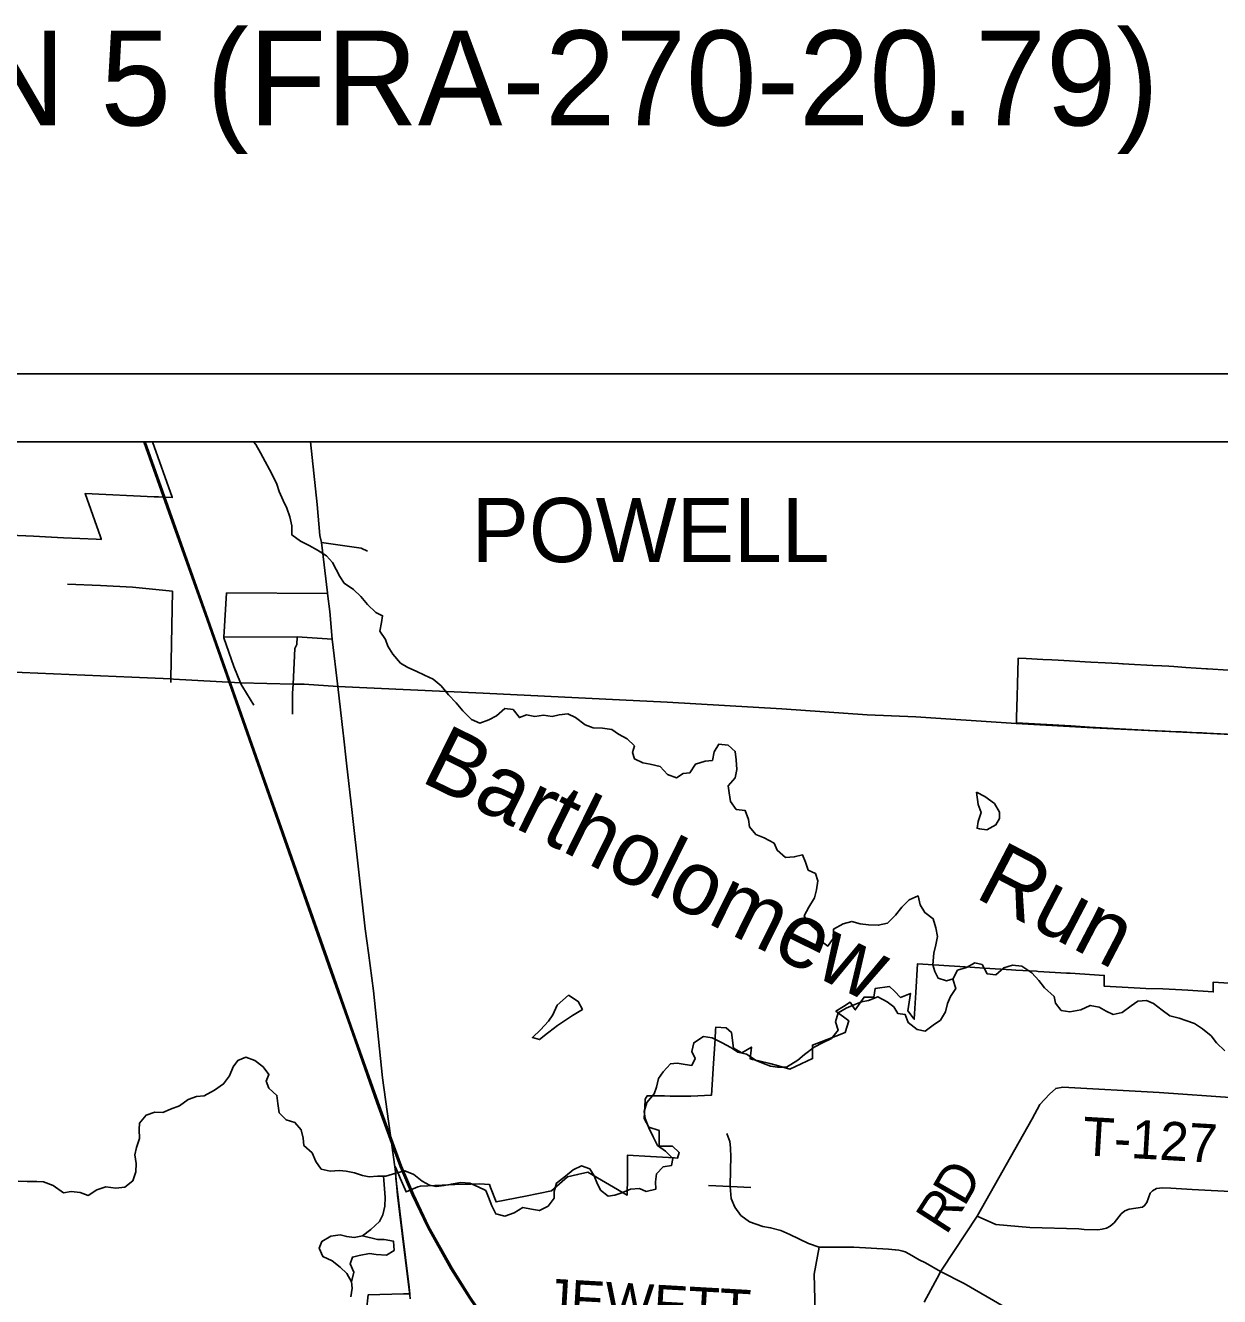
# Model space of a CAD drawing. Extents: x 0 to 34, y 0 to 22.
# Drawn here: x 15.645 to 17.407, y 8.924 to 10.798 of the extents above; entities that cross this region are included whole.
import ezdxf

# ---------------------------------------------------------------- set-up
doc = ezdxf.new("R2010")
doc.units = 0
for name, color, linetype in [('Default', 7, 'Continuous'), ('GM_X_City_Street', 7, 'Continuous'), ('GM_X_Corporation', 7, 'Continuous'), ('GM_X_Corporation_Text', 7, 'Continuous'), ('GM_X_County_Road', 7, 'Continuous'), ('GM_X_Minor_Lake', 7, 'Continuous'), ('GM_X_Minor_River', 7, 'Continuous'), ('GM_X_Minor_River_Text', 7, 'Continuous'), ('GM_X_Rail_Line', 7, 'Continuous'), ('GM_X_State_Route', 7, 'Continuous'), ('GM_X_Township_Road', 7, 'Continuous'), ('GM_X_Township_Road_Text', 7, 'Continuous'), ('SH_Data', 7, 'Continuous')]:
    doc.layers.add(name, color=color, linetype=linetype)

msp = doc.modelspace()

# ---------------------------------------------------------------- linework, layer by layer
at = {"layer": 'GM_X_City_Street'}
msp.add_line((15.942, 9.9613), (16.0909, 9.9604), dxfattribs=at)
for points in [[(16.0821, 10.0353), (16.1403, 10.0271), (16.1498, 10.0225)], [(15.7076, 9.9739), (15.7561, 9.9721), (15.8034, 9.9696), (15.8625, 9.9639)], [(15.8596, 9.8293), (15.8597, 9.8344), (15.8625, 9.9639)], [(15.9823, 9.7959), (15.9658, 9.8224), (15.9641, 9.825), (15.9626, 9.8287), (15.9527, 9.8525), (15.9381, 9.8949), (15.9382, 9.8961), (15.942, 9.9613)], [(15.9382, 9.8961), (16.046, 9.8964), (16.098, 9.8932)], [(16.0393, 9.8132), (16.04, 9.8268), (16.0427, 9.8792), (16.0457, 9.8849), (16.046, 9.8964)], [(16.0393, 9.7822), (16.0393, 9.8121), (16.0393, 9.8132)]]:
    msp.add_lwpolyline(points, dxfattribs=at)
at = {"layer": 'GM_X_Corporation'}
for points in [[(15.3473, 8.5302), (16.0546, 8.4904), (16.2652, 8.4813), (16.5003, 8.4668), (16.6112, 8.4601), (16.8906, 8.4459), (17.9061, 8.3935), (17.9129, 8.3931), (18.0835, 8.3895), (18.0903, 8.3893), (19.1791, 8.3374), (19.2255, 8.335), (19.3372, 8.3286), (19.3853, 8.3266), (19.4457, 8.3236), (19.4724, 8.3227), (19.4766, 8.3225), (19.5203, 8.3202), (19.5346, 8.3197), (19.5646, 8.318), (19.5646, 10.1841), (12.7646, 10.1841)], [(15.3473, 8.5302), (16.0546, 8.4904), (16.2652, 8.4813), (16.5003, 8.4668), (16.6112, 8.4601), (16.8906, 8.4459), (17.9061, 8.3935), (17.9129, 8.3931), (17.9187, 8.5404), (17.9296, 8.8181), (17.9647, 9.7099), (17.9872, 10.1841), (13.2832, 10.1841)], [(17.8098, 10.1841), (15.833, 10.1841), (15.8618, 10.1025), (15.8621, 10.1018), (15.8418, 10.1027), (15.835, 10.1031), (15.7337, 10.1076), (15.7334, 10.1076), (15.7559, 10.0439), (15.7571, 10.0407), (15.7573, 10.04), (15.7498, 10.0403), (15.7014, 10.0426), (15.6838, 10.0434), (15.6572, 10.0447), (15.5762, 10.0485)], [(17.4378, 9.752), (17.3878, 9.7544), (17.381, 9.7547), (17.366, 9.7554), (17.3506, 9.7562), (17.3345, 9.7569), (17.3261, 9.7572), (17.3039, 9.7584), (17.2149, 9.7632), (17.1871, 9.7652), (17.1068, 9.7694), (17.1068, 9.77), (17.107, 9.7754), (17.1071, 9.7775), (17.108, 9.8085), (17.1086, 9.8269), (17.1091, 9.8452), (17.1097, 9.8636), (17.1097, 9.865), (17.1211, 9.8644), (17.1457, 9.8631), (17.1591, 9.8624), (17.1683, 9.8619), (17.1854, 9.8609), (17.2005, 9.8601), (17.2082, 9.8597), (17.2166, 9.8592), (17.2377, 9.8581), (17.2573, 9.857), (17.2633, 9.8567), (17.2642, 9.8567), (17.2813, 9.8557), (17.2993, 9.8548), (17.3082, 9.8543), (17.3215, 9.8536), (17.3319, 9.853), (17.339, 9.8526), (17.3569, 9.8512), (17.3873, 9.8494), (17.3888, 9.8493), (17.4199, 9.8475)], [(16.1484, 8.9035), (16.151, 8.9262), (16.2028, 8.9276), (16.2075, 8.9277), (16.2123, 8.9278), (16.2111, 8.9373), (16.2058, 8.9811), (16.2015, 9.0173), (16.1917, 9.0983), (16.1908, 9.1156), (16.1908, 9.1156), (16.196, 9.103), (16.1979, 9.0984), (16.2052, 9.0813), (16.2068, 9.0778), (16.2242, 9.0852), (16.2278, 9.0866), (16.26, 9.0879), (16.2789, 9.0889), (16.3022, 9.0895), (16.3149, 9.0897), (16.3296, 9.0889), (16.3314, 9.0842), (16.3396, 9.0631), (16.3828, 9.0718), (16.4211, 9.0796), (16.4447, 9.0999), (16.4597, 9.1034), (16.4748, 9.107), (16.5329, 9.0732), (16.533, 9.0848), (16.5331, 9.0873), (16.5335, 9.1321), (16.5671, 9.1302), (16.6028, 9.1281), (16.6071, 9.1279), (16.6097, 9.1362), (16.5997, 9.1452), (16.5798, 9.1456), (16.58, 9.1686), (16.565, 9.1734), (16.5581, 9.1861), (16.5588, 9.2026), (16.5594, 9.2145), (16.5622, 9.2195), (16.5879, 9.2196), (16.5962, 9.2192), (16.6266, 9.2192), (16.6571, 9.2204), (16.6597, 9.2594), (16.6597, 9.2599), (16.6624, 9.3035), (16.6633, 9.3168), (16.6635, 9.3207), (16.6786, 9.3197), (16.6865, 9.313), (16.6899, 9.2897), (16.7021, 9.2832), (16.7161, 9.2914), (16.7141, 9.2742), (16.7178, 9.2733), (16.7269, 9.2711), (16.7433, 9.2672), (16.7527, 9.2646), (16.7728, 9.2591), (16.8062, 9.2744), (16.806, 9.2943), (16.8408, 9.3077), (16.8544, 9.313), (16.8597, 9.3303), (16.8407, 9.3443), (16.8519, 9.3514), (16.8615, 9.3575), (16.8692, 9.3463), (16.8822, 9.3652), (16.8968, 9.3649), (16.8986, 9.3781), (16.9197, 9.3808), (16.9269, 9.3737), (16.9361, 9.3646), (16.9506, 9.3705), (16.9467, 9.3447), (16.9562, 9.3325), (16.9585, 9.3719), (16.961, 9.4142), (17.0311, 9.4098), (17.0599, 9.408), (17.0995, 9.4055), (17.1061, 9.4051), (17.1364, 9.4032), (17.1391, 9.4031), (17.1808, 9.4007), (17.1864, 9.4003), (17.2364, 9.3971), (17.2364, 9.3812), (17.2893, 9.3783), (17.298, 9.3778), (17.3229, 9.3775), (17.3511, 9.3757), (17.3599, 9.3752), (17.3971, 9.3729), (17.3972, 9.3835), (17.3972, 9.3873), (17.4207, 9.3859)]]:
    msp.add_lwpolyline(points, dxfattribs=at)
at = {"layer": 'GM_X_County_Road'}
msp.add_line((16.1138, 9.7546), (16.1062, 9.8233), dxfattribs=at)
for points in [[(16.0908, 9.9614), (16.0821, 10.0353), (16.0795, 10.046), (16.0758, 10.0915), (16.0659, 10.1841)], [(16.1062, 9.8233), (16.098, 9.8932), (16.0945, 9.9337), (16.0909, 9.9604), (16.0908, 9.9614)], [(16.1513, 9.4305), (16.1464, 9.466), (16.1274, 9.6375), (16.1188, 9.7102), (16.1143, 9.7506), (16.1138, 9.7546)], [(16.1911, 9.107), (16.1903, 9.115), (16.1721, 9.2462), (16.1589, 9.3743), (16.1513, 9.4305)], [(16.1996, 9.0283), (16.1942, 9.0731), (16.1911, 9.107)], [(16.2128, 8.9204), (16.2121, 8.9262), (16.2053, 8.9805), (16.201, 9.0167), (16.1996, 9.0283)]]:
    msp.add_lwpolyline(points, dxfattribs=at)
at = {"layer": 'GM_X_Minor_Lake'}
for points in [[(17.048, 9.6672), (17.0507, 9.649), (17.0548, 9.6372), (17.0507, 9.6243), (17.0488, 9.6141), (17.0525, 9.6135)], [(17.0525, 9.6135), (17.0632, 9.6118), (17.0768, 9.619), (17.0821, 9.6285), (17.0821, 9.638), (17.0745, 9.6505), (17.0605, 9.6608), (17.048, 9.6672)], [(16.4464, 9.3678), (16.4298, 9.3534), (16.423, 9.339), (16.4169, 9.3295), (16.4052, 9.317), (16.3931, 9.3056), (16.4037, 9.3026), (16.4154, 9.312)], [(16.4154, 9.312), (16.4173, 9.3136), (16.4302, 9.3231), (16.4521, 9.3382), (16.4669, 9.347), (16.4608, 9.3587), (16.4464, 9.3678)], [(16.1423, 9.0129), (16.1302, 9.0106), (16.1192, 9.0121), (16.1094, 9.0144), (16.0958, 9.0125), (16.0825, 9.0049), (16.0787, 8.9951), (16.084, 8.9826), (16.0977, 8.9761), (16.1094, 8.967), (16.1196, 8.9575), (16.1265, 8.9453)], [(16.1265, 8.9453), (16.1295, 8.9598), (16.1242, 8.9719), (16.1276, 8.9818), (16.1374, 8.984), (16.1529, 8.9871), (16.1628, 8.9855), (16.1779, 8.9844), (16.1893, 8.9916), (16.1881, 9.0053), (16.1745, 9.0075), (16.1646, 9.0079), (16.1423, 9.0129)]]:
    msp.add_lwpolyline(points, dxfattribs=at)
at = {"layer": 'GM_X_Minor_River'}
for points in [[(16.1801, 9.8828), (16.1763, 9.8923), (16.168, 9.9049), (16.1706, 9.9174), (16.1721, 9.9276), (16.1623, 9.9325), (16.1498, 9.9439), (16.14, 9.9561), (16.129, 9.966), (16.1157, 9.9758), (16.1093, 9.9853), (16.1036, 9.9956), (16.0983, 10.0058), (16.0892, 10.0161), (16.076, 10.0244), (16.0638, 10.0312), (16.051, 10.0373), (16.0385, 10.0468), (16.0381, 10.0601), (16.0354, 10.0734), (16.0309, 10.0863), (16.0256, 10.0973), (16.0195, 10.1106), (16.0161, 10.1216), (16.0119, 10.131), (16.0055, 10.1432), (15.9991, 10.1549), (15.9922, 10.1679), (15.9851, 10.18), (15.9816, 10.1841)], [(17.0134, 9.392), (17.0039, 9.3891), (16.9917, 9.3929), (16.9868, 9.4028), (16.9838, 9.4126), (16.9853, 9.4301), (16.9883, 9.4422), (16.9906, 9.4544), (16.9883, 9.4673), (16.9841, 9.4806), (16.9716, 9.4897), (16.9648, 9.5011), (16.9618, 9.5143), (16.9489, 9.5087), (16.9379, 9.4977), (16.9285, 9.4859), (16.9168, 9.4742), (16.9031, 9.4711), (16.8888, 9.4715), (16.8767, 9.4734), (16.8642, 9.4768), (16.8513, 9.4731), (16.8373, 9.4655), (16.8365, 9.4514), (16.8286, 9.4404), (16.8169, 9.4492), (16.8135, 9.4625), (16.801, 9.4735), (16.7941, 9.4849), (16.8006, 9.4977), (16.8093, 9.5114), (16.8119, 9.5232), (16.8142, 9.5364), (16.8104, 9.5474), (16.7998, 9.5524), (16.796, 9.5642), (16.7915, 9.5748), (16.7793, 9.5718), (16.7665, 9.571), (16.754, 9.5816), (16.7494, 9.5923), (16.7351, 9.6002), (16.7226, 9.6048), (16.7135, 9.6162), (16.712, 9.6272), (16.707, 9.6401), (16.6938, 9.642), (16.6851, 9.6538), (16.6835, 9.6663), (16.682, 9.6765), (16.6919, 9.6887), (16.6945, 9.7008), (16.6937, 9.7148), (16.6922, 9.7274), (16.682, 9.7365), (16.668, 9.738), (16.6612, 9.727), (16.6585, 9.7141), (16.648, 9.713), (16.6336, 9.7088), (16.6253, 9.6959), (16.6154, 9.6948), (16.6056, 9.6887), (16.5923, 9.6933), (16.5814, 9.705), (16.5666, 9.7088), (16.556, 9.7108), (16.5435, 9.7165), (16.5408, 9.7259), (16.5435, 9.7358), (16.5329, 9.7461), (16.52, 9.7529), (16.5102, 9.7597), (16.4965, 9.7616), (16.4829, 9.7624), (16.4708, 9.7666), (16.4568, 9.7776), (16.4451, 9.7829), (16.4326, 9.7814), (16.422, 9.7791), (16.4095, 9.7807), (16.3966, 9.7791), (16.3845, 9.7814), (16.3739, 9.7773), (16.3645, 9.7894), (16.3523, 9.7905), (16.3399, 9.7799), (16.3289, 9.7739), (16.3156, 9.7693), (16.3032, 9.7743), (16.2907, 9.7875), (16.2804, 9.7989), (16.2695, 9.8107), (16.2585, 9.824), (16.2467, 9.8339), (16.2339, 9.8399), (16.2214, 9.846), (16.2096, 9.8513), (16.1983, 9.8578), (16.1873, 9.8711), (16.1801, 9.8828)], [(17.4145, 9.2861), (17.402, 9.2978), (17.3941, 9.3081), (17.3816, 9.3183), (17.3695, 9.3263), (17.357, 9.3305), (17.3468, 9.3343), (17.3331, 9.3377), (17.3218, 9.3461), (17.3089, 9.3559), (17.2987, 9.3601), (17.2858, 9.3594), (17.276, 9.3525), (17.2627, 9.3423), (17.2495, 9.3396), (17.2393, 9.3446), (17.229, 9.3503), (17.2158, 9.3529), (17.2018, 9.3465), (17.1855, 9.3435), (17.173, 9.3454), (17.1647, 9.3564), (17.1628, 9.3659), (17.1484, 9.3788), (17.1401, 9.3898), (17.1295, 9.4008), (17.1151, 9.411), (17.1011, 9.4122), (17.0886, 9.4084), (17.0765, 9.3982), (17.0636, 9.3997), (17.0564, 9.4134), (17.0455, 9.4156), (17.0334, 9.4088), (17.0201, 9.4047), (17.0133, 9.3918), (17.0175, 9.3781), (17.0095, 9.3663), (17.0054, 9.3557), (17.0024, 9.3436), (16.9948, 9.3311), (16.9842, 9.3239), (16.9721, 9.3151), (16.9607, 9.3174), (16.9475, 9.3277), (16.9429, 9.3394), (16.932, 9.341), (16.9259, 9.3508), (16.9161, 9.358), (16.9024, 9.3656), (16.8888, 9.36), (16.8786, 9.3581), (16.8688, 9.3543), (16.8559, 9.349), (16.8438, 9.3418), (16.84, 9.3285), (16.8438, 9.3164), (16.834, 9.3042), (16.8211, 9.2978), (16.8086, 9.2913), (16.7946, 9.2803), (16.7844, 9.2724), (16.7678, 9.2618), (16.7545, 9.2618), (16.7443, 9.2633)], [(16.7443, 9.2633), (16.7341, 9.2675), (16.7231, 9.2717), (16.7087, 9.2808), (16.6962, 9.2842), (16.6856, 9.291), (16.6728, 9.2979), (16.658, 9.3051), (16.6455, 9.307), (16.6311, 9.2979), (16.6281, 9.285), (16.633, 9.2748), (16.6281, 9.2645), (16.6183, 9.266), (16.6065, 9.2679), (16.5967, 9.2668), (16.5857, 9.2551), (16.5789, 9.2452), (16.5763, 9.2323), (16.5725, 9.2224), (16.5619, 9.2099), (16.5578, 9.1966), (16.5593, 9.1864), (16.565, 9.1724), (16.5714, 9.1591), (16.5778, 9.1465), (16.5892, 9.1382), (16.6002, 9.1272), (16.5983, 9.1169), (16.5858, 9.115), (16.576, 9.1044), (16.5748, 9.093), (16.5752, 9.082), (16.5608, 9.0786), (16.551, 9.0828), (16.5378, 9.0821), (16.5249, 9.0764), (16.5147, 9.073), (16.5048, 9.0715), (16.4935, 9.0806), (16.4882, 9.092), (16.4844, 9.1018), (16.4776, 9.1121), (16.4655, 9.1163), (16.4534, 9.1106), (16.442, 9.1011), (16.4284, 9.0909), (16.4254, 9.0787), (16.425, 9.0689), (16.4163, 9.0567), (16.4034, 9.0503), (16.3917, 9.0526), (16.3792, 9.0548), (16.3663, 9.0473), (16.3523, 9.0423), (16.3391, 9.0454), (16.3334, 9.0572), (16.3285, 9.0701), (16.3243, 9.0799), (16.313, 9.0856), (16.3008, 9.0906), (16.2872, 9.0917), (16.2736, 9.0894), (16.263, 9.0876), (16.2509, 9.0857), (16.2411, 9.0879), (16.2305, 9.0936), (16.218, 9.1035), (16.2047, 9.1088), (16.1918, 9.1054), (16.1771, 9.1009), (16.1646, 9.1009), (16.1525, 9.1001), (16.1423, 9.102), (16.1305, 9.1062), (16.1184, 9.1085), (16.1086, 9.1096), (16.095, 9.1085), (16.0817, 9.1116), (16.0738, 9.1226), (16.0685, 9.1355), (16.056, 9.1461), (16.0548, 9.1571), (16.0522, 9.1693), (16.0427, 9.1803), (16.0298, 9.1844), (16.0196, 9.1947), (16.0177, 9.2083), (16.0162, 9.2201), (16.0044, 9.2311), (16.0003, 9.2414), (16.0044, 9.2512), (15.9961, 9.2622), (15.9836, 9.2717), (15.9704, 9.2767), (15.9586, 9.2717), (15.9518, 9.2623), (15.9465, 9.249), (15.9375, 9.2372), (15.9242, 9.2277), (15.9091, 9.2194)], [(15.9091, 9.2194), (15.8977, 9.2187), (15.8852, 9.2141), (15.8728, 9.205), (15.8595, 9.1997), (15.8482, 9.1948), (15.8364, 9.1955), (15.8232, 9.191), (15.8137, 9.1792), (15.813, 9.1698), (15.8137, 9.1569), (15.8092, 9.1436), (15.8066, 9.1326), (15.8085, 9.1197), (15.8081, 9.1075), (15.8039, 9.0943), (15.7918, 9.0848), (15.7786, 9.0833), (15.7642, 9.0852), (15.7506, 9.081), (15.7381, 9.0727), (15.726, 9.0768), (15.7127, 9.0784), (15.7014, 9.0765), (15.6862, 9.0875), (15.6722, 9.0928), (15.662, 9.0932), (15.648, 9.0932), (15.6348, 9.0939)], [(16.1737, 9.1009), (16.1741, 9.0952), (16.1748, 9.0823), (16.176, 9.0698), (16.1756, 9.0569), (16.1726, 9.044), (16.1677, 9.0345), (16.1548, 9.0224), (16.1423, 9.0129), (16.1302, 9.0106), (16.1192, 9.0121), (16.1094, 9.0144), (16.0958, 9.0125), (16.0825, 9.0049), (16.0787, 8.9951), (16.084, 8.9826), (16.0977, 8.9761), (16.1094, 8.967), (16.1196, 8.9575), (16.1265, 8.9453), (16.1272, 8.9359), (16.1253, 8.923)]]:
    msp.add_lwpolyline(points, dxfattribs=at)
at = {"layer": 'GM_X_Rail_Line'}
for points in [[(16.6916, 8.4543), (16.6646, 8.4903), (16.6063, 8.5579), (16.4536, 8.7316), (16.4089, 8.7825), (16.3706, 8.8265), (16.3479, 8.855), (16.3321, 8.8758), (16.316, 8.8981), (16.3002, 8.9211), (16.273, 8.9643), (16.2388, 9.0256), (16.2159, 9.0737), (16.1982, 9.1153), (16.1872, 9.1446), (16.1638, 9.2095), (16.1241, 9.3217), (16.0955, 9.4034), (15.9132, 9.9213), (15.854, 10.0881), (15.8202, 10.1841)], [(16.6931, 8.4555), (16.6661, 8.4914), (16.6077, 8.5592), (16.4551, 8.7329), (16.4103, 8.7837), (16.3721, 8.8277), (16.3494, 8.8562), (16.3337, 8.8769), (16.3175, 8.8992), (16.3018, 8.9221), (16.2747, 8.9653), (16.2404, 9.0265), (16.2176, 9.0745), (16.2, 9.116), (16.189, 9.1452), (16.1656, 9.2101), (16.1259, 9.3223), (16.0973, 9.404), (15.915, 9.9219), (15.8558, 10.0887), (15.8222, 10.1841)]]:
    msp.add_lwpolyline(points, dxfattribs=at)
at = {"layer": 'GM_X_State_Route'}
for points in [[(15.4875, 9.852), (15.5941, 9.8457), (15.8025, 9.8371), (15.8597, 9.8344), (15.8637, 9.8342), (15.9626, 9.8287), (16.04, 9.8268), (16.0564, 9.8264), (16.1062, 9.8233)], [(16.1062, 9.8233), (16.3203, 9.8132), (16.5918, 9.7999), (16.7609, 9.7904), (16.8869, 9.7812), (16.9585, 9.7783), (17.0993, 9.7693)], [(17.0993, 9.7693), (17.1064, 9.7688), (17.22, 9.7624), (17.4436, 9.7512)]]:
    msp.add_lwpolyline(points, dxfattribs=at)
at = {"layer": 'GM_X_Township_Road'}
for points in [[(16.9709, 8.9154), (16.9934, 8.9571), (16.995, 8.9605), (16.9973, 8.964), (17.0491, 9.0423), (17.1301, 9.1859), (17.1414, 9.2067), (17.1556, 9.2222), (17.165, 9.2306), (17.1754, 9.2324), (17.3175, 9.2244), (17.5407, 9.2088), (17.5686, 9.2108), (17.6382, 9.2067), (17.6571, 9.2056), (17.6812, 9.2025), (17.7099, 9.1965), (17.762, 9.184), (17.7893, 9.1797)], [(16.995, 8.9605), (16.9726, 8.9731), (16.9635, 8.9778), (16.9494, 8.9862), (16.9428, 8.9894), (16.9392, 8.9905), (16.9335, 8.9918), (16.9281, 8.9927), (16.9181, 8.9933), (16.867, 8.9963), (16.8161, 8.9966), (16.8003, 9.0018), (16.7729, 9.015), (16.7595, 9.0211), (16.7444, 9.025), (16.7328, 9.0269), (16.7135, 9.0336), (16.7005, 9.0433), (16.6916, 9.0552), (16.6861, 9.0684), (16.6848, 9.086), (16.6852, 9.1109), (16.6858, 9.1291), (16.6852, 9.1429), (16.6842, 9.1522), (16.6798, 9.1639)], [(16.6526, 9.0876), (16.6848, 9.086), (16.7151, 9.0846)], [(17.0491, 9.0423), (17.0764, 9.0297), (17.1268, 9.0252), (17.1989, 9.0237), (17.2066, 9.0226), (17.2269, 9.0222), (17.2333, 9.0228), (17.2396, 9.0246), (17.2454, 9.0275), (17.2513, 9.0324), (17.2616, 9.0455), (17.2668, 9.0502), (17.2734, 9.0525), (17.2927, 9.0554), (17.296, 9.0577), (17.2992, 9.0622), (17.3044, 9.076), (17.3074, 9.0794), (17.3133, 9.0828), (17.3226, 9.0839), (17.3348, 9.0834), (17.3663, 9.0816), (17.432, 9.0779)], [(16.8112, 8.8488), (16.8102, 8.9013), (16.8084, 8.9565), (16.8161, 8.9966)], [(17.0317, 8.8186), (17.0625, 8.8193), (17.07, 8.8202), (17.0836, 8.8241), (17.0939, 8.8308), (17.1003, 8.8374), (17.1042, 8.8436), (17.1083, 8.8528), (17.1105, 8.8605), (17.1108, 8.8712), (17.1065, 8.8877), (17.1017, 8.8965), (17.0954, 8.9035), (17.0886, 8.9091), (17.0299, 8.9428), (16.995, 8.9605)]]:
    msp.add_lwpolyline(points, dxfattribs=at)
at = {"layer": 'SH_Data'}
for p, q in [((12.6646, 10.2841), (19.6646, 10.2841)), ((12.7646, 10.1841), (19.5646, 10.1841))]:
    msp.add_line(p, q, dxfattribs=at)

# ---------------------------------------------------------------- texts
at = {"layer": 'Default'}
msp.add_text('LOCATION 5 (FRA-270-20.79)', height=0.14, dxfattribs=at).set_placement((14.7471, 10.6505))
at = {"layer": 'GM_X_Corporation_Text'}
msp.add_text('POWELL', height=0.0947, rotation=0, dxfattribs=at).set_placement((16.3034, 10.0066))
at = {"layer": 'GM_X_Minor_River_Text'}
for s, rotation, p in [('Bartholomew', 333.6958, (16.2261, 9.6842)), ('Run', 332.4029, (17.0434, 9.5132))]:
    msp.add_text(s, height=0.0947, rotation=rotation, dxfattribs=at).set_placement(p)
at = {"layer": 'GM_X_Township_Road_Text'}
for s, height, rotation, p in [('T-127', 0.05682, 356.6673, (17.2032, 9.1321)), ('D', 0.0568, 60.0129, (17.0301, 9.0548)), ('R', 0.0568, 57.2344, (17.0033, 9.013)), ('JEWETT', 0.05682, 356.7399, (16.41, 8.8937))]:
    msp.add_text(s, height=height, rotation=rotation, dxfattribs=at).set_placement(p)

doc.saveas('drawing.dxf')
